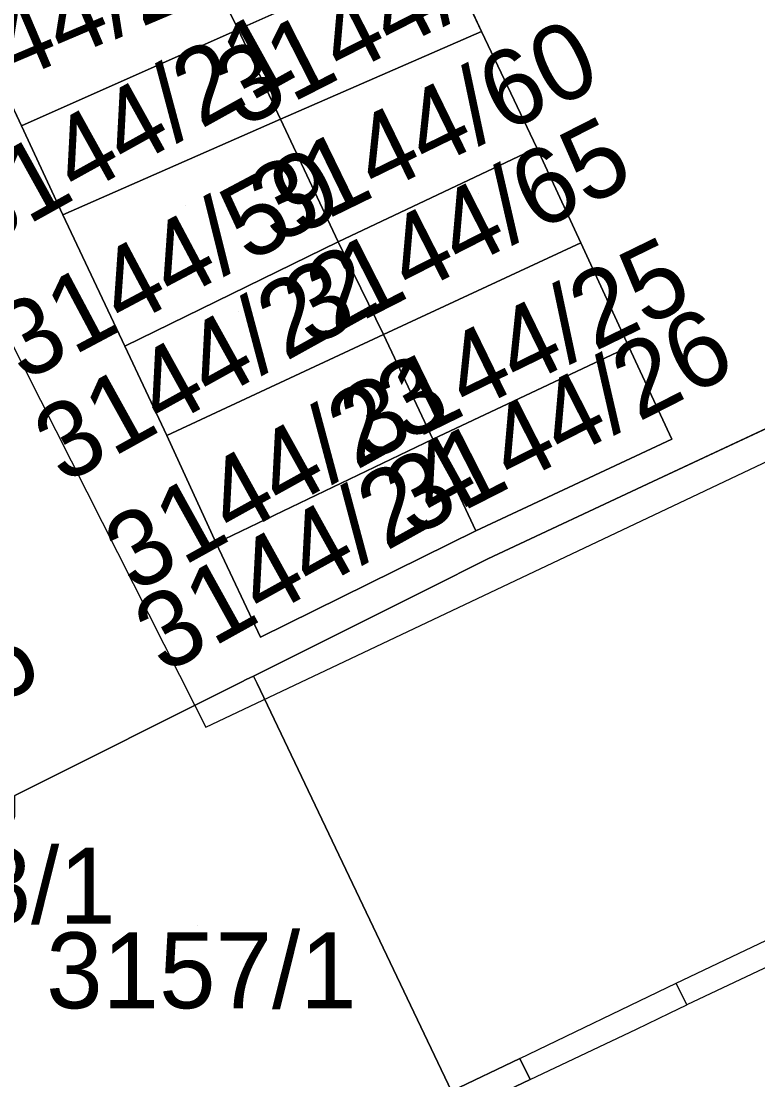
# Model space of a CAD drawing. Extents: x -264070 to -262271, y -1238894 to -1238141.
# Drawn here: x -262997.5 to -262978.09, y -1238467.13 to -1238439.24 of the extents above; entities that cross this region are included whole.
import ezdxf

# ---------------------------------------------------------------- set-up
doc = ezdxf.new("R2010")
doc.units = 0
for name, color, linetype in [('body_kn', 7, 'Continuous'), ('kladpar_druhypozemkov', 7, 'Continuous'), ('kladpar_hranice', 7, 'Continuous'), ('kladpar_parcelnecisla', 7, 'Continuous'), ('kladpar_plochy', 7, 'Continuous'), ('tarchy_linie', 7, 'Continuous'), ('zappar_hrandruhpozemk', 7, 'Continuous')]:
    doc.layers.add(name, color=color, linetype=linetype)

msp = doc.modelspace()

# ---------------------------------------------------------------- linework, layer by layer
at = {"layer": 'body_kn'}
for p, q in [((-262991.78, -1238439.46), (-262991.78, -1238439.46)), ((-262991.78, -1238439.46), (-262991.78, -1238439.46)), ((-262985.37, -1238439.52), (-262985.37, -1238439.52)), ((-262985.37, -1238439.52), (-262985.37, -1238439.52)), ((-262997.49, -1238442), (-262997.49, -1238442)), ((-262990.67, -1238441.83), (-262990.67, -1238441.83)), ((-262990.67, -1238441.83), (-262990.67, -1238441.83)), ((-262983.91, -1238442.58), (-262983.91, -1238442.58)), ((-262983.91, -1238442.58), (-262983.91, -1238442.58)), ((-262996.4, -1238444.35), (-262996.4, -1238444.35)), ((-262989.15, -1238445.06), (-262989.15, -1238445.06)), ((-262989.15, -1238445.06), (-262989.15, -1238445.06)), ((-262982.75, -1238445.08), (-262982.75, -1238445.08)), ((-262982.75, -1238445.08), (-262982.75, -1238445.08)), ((-262987.95, -1238447.5), (-262987.95, -1238447.5)), ((-262987.95, -1238447.5), (-262987.95, -1238447.5)), ((-262994.77, -1238447.81), (-262994.77, -1238447.81)), ((-262981.49, -1238447.82), (-262981.49, -1238447.82)), ((-262981.49, -1238447.82), (-262981.49, -1238447.82)), ((-262993.66, -1238450.16), (-262993.66, -1238450.16)), ((-262986.65, -1238450.26), (-262986.65, -1238450.26)), ((-262986.65, -1238450.26), (-262986.65, -1238450.26)), ((-262980.36, -1238450.26), (-262980.36, -1238450.26)), ((-262980.86, -1238451.37), (-262980.86, -1238451.37)), ((-262980.82, -1238452.25), (-262980.82, -1238452.25)), ((-262985.52, -1238452.67), (-262985.52, -1238452.67)), ((-262992.36, -1238453), (-262992.36, -1238453)), ((-262985.2, -1238453.41), (-262985.2, -1238453.41)), ((-262986.78, -1238454.2), (-262986.78, -1238454.2)), ((-262991.19, -1238455.47), (-262991.19, -1238455.47)), ((-262991.38, -1238456.5), (-262991.38, -1238456.5)), ((-262991.69, -1238456.65), (-262991.69, -1238456.65)), ((-262991.57, -1238456.59), (-262991.57, -1238456.59)), ((-262991.28, -1238456.69), (-262991.28, -1238456.69)), ((-262992.92, -1238457.27), (-262992.92, -1238457.27)), ((-262992.92, -1238457.27), (-262992.92, -1238457.27)), ((-262992.63, -1238457.84), (-262992.63, -1238457.84)), ((-262980.24, -1238464.59), (-262980.24, -1238464.59)), ((-262979.96, -1238465.16), (-262979.96, -1238465.16)), ((-262979.96, -1238465.16), (-262979.96, -1238465.16)), ((-262980.42, -1238465.38), (-262980.42, -1238465.38)), ((-262981.29, -1238465.8), (-262981.29, -1238465.8)), ((-262984.36, -1238466.57), (-262984.36, -1238466.57)), ((-262984.36, -1238466.57), (-262984.36, -1238466.57)), ((-262984.09, -1238467.13), (-262984.09, -1238467.13)), ((-262984.09, -1238467.13), (-262984.09, -1238467.13))]:
    msp.add_line(p, q, dxfattribs=at)
at = {"layer": 'kladpar_druhypozemkov'}
for p, q in [((-262994.57, -1238441.2), (-262994.57, -1238441.2)), ((-262986.96, -1238440.96), (-262986.96, -1238440.96)), ((-262985.46, -1238443.79), (-262985.46, -1238443.79)), ((-262993.17, -1238444.1), (-262993.17, -1238444.1)), ((-262983.29, -1238446.74), (-262983.29, -1238446.74)), ((-262991.77, -1238446.9), (-262991.77, -1238446.9)), ((-262983.2, -1238449.11), (-262983.2, -1238449.11)), ((-262992.21, -1238451.03), (-262992.21, -1238451.03)), ((-262988.77, -1238451.7), (-262988.77, -1238451.7)), ((-262992.85, -1238463.08), (-262992.85, -1238463.08))]:
    msp.add_line(p, q, dxfattribs=at)
at = {"layer": 'kladpar_hranice'}
for points in [[(-262994.77, -1238447.81), (-262993.66, -1238450.16), (-262992.36, -1238453), (-262991.19, -1238455.47), (-262985.52, -1238452.67), (-262980.36, -1238450.26), (-262981.49, -1238447.82), (-262982.75, -1238445.08), (-262983.91, -1238442.58), (-262985.37, -1238439.52), (-262986.49, -1238437.1), (-262987.81, -1238434.35), (-262989.09, -1238431.69), (-262990.18, -1238429.37), (-262995.49, -1238431.89), (-263000.98, -1238434.56), (-263000.02, -1238436.62), (-262998.8, -1238439.23), (-262997.49, -1238442), (-262996.4, -1238444.35), (-262994.77, -1238447.81)], [(-262987.81, -1238434.35), (-262986.49, -1238437.1), (-262991.78, -1238439.46), (-262993.13, -1238436.72), (-262987.81, -1238434.35)], [(-262993.13, -1238436.72), (-262991.78, -1238439.46), (-262997.49, -1238442), (-262998.8, -1238439.23), (-262993.13, -1238436.72)], [(-262986.49, -1238437.1), (-262985.37, -1238439.52), (-262990.67, -1238441.83), (-262991.78, -1238439.46), (-262986.49, -1238437.1)], [(-262991.78, -1238439.46), (-262990.67, -1238441.83), (-262996.4, -1238444.35), (-262997.49, -1238442), (-262991.78, -1238439.46)], [(-262985.37, -1238439.52), (-262983.91, -1238442.58), (-262989.15, -1238445.06), (-262990.67, -1238441.83), (-262985.37, -1238439.52)], [(-262990.67, -1238441.83), (-262989.15, -1238445.06), (-262994.77, -1238447.81), (-262996.4, -1238444.35), (-262990.67, -1238441.83)], [(-262983.91, -1238442.58), (-262982.75, -1238445.08), (-262987.95, -1238447.5), (-262989.15, -1238445.06), (-262983.91, -1238442.58)], [(-262965.85, -1238444.36), (-262980.86, -1238451.37), (-262985.2, -1238453.41), (-262986.78, -1238454.2), (-262991.38, -1238456.5), (-262991.57, -1238456.59), (-262991.69, -1238456.65), (-262997.67, -1238459.64)], [(-262985.45, -1238467.78), (-262984.09, -1238467.13), (-262984.36, -1238466.57), (-262986.16, -1238467.43), (-262991.28, -1238456.69), (-262991.38, -1238456.5), (-262986.78, -1238454.2), (-262985.2, -1238453.41), (-262980.86, -1238451.37), (-262965.85, -1238444.36), (-262960.55, -1238455.19), (-262970.92, -1238460.15), (-262970.64, -1238460.72)], [(-262989.15, -1238445.06), (-262987.95, -1238447.5), (-262993.66, -1238450.16), (-262994.77, -1238447.81), (-262989.15, -1238445.06)], [(-262982.75, -1238445.08), (-262981.49, -1238447.82), (-262986.65, -1238450.26), (-262987.95, -1238447.5), (-262982.75, -1238445.08)], [(-262987.95, -1238447.5), (-262986.65, -1238450.26), (-262992.36, -1238453), (-262993.66, -1238450.16), (-262987.95, -1238447.5)], [(-262981.49, -1238447.82), (-262980.36, -1238450.26), (-262985.52, -1238452.67), (-262986.65, -1238450.26), (-262981.49, -1238447.82)], [(-262986.65, -1238450.26), (-262985.52, -1238452.67), (-262991.19, -1238455.47), (-262992.36, -1238453), (-262986.65, -1238450.26)], [(-262997.67, -1238459.64), (-262991.69, -1238456.65), (-262991.57, -1238456.59), (-262991.38, -1238456.5), (-262991.28, -1238456.69), (-262986.16, -1238467.43), (-262984.36, -1238466.57), (-262984.09, -1238467.13), (-262985.45, -1238467.78), (-262986.48, -1238468.27), (-262987.33, -1238468.68), (-262993.76, -1238471.75), (-262994.32, -1238472.02), (-262995.94, -1238472.79), (-262997.16, -1238473.37), (-262997.34, -1238473.03), (-262997.51, -1238472.71), (-263001.85, -1238464.06), (-262998.96, -1238462.59), (-262998.09, -1238461.48), (-262997.67, -1238460.19), (-262997.67, -1238459.64)]]:
    msp.add_lwpolyline(points, dxfattribs=at)
at = {"layer": 'kladpar_plochy'}
for p, q in [((-262985.37, -1238439.52), (-262986.49, -1238437.1)), ((-262998.8, -1238439.23), (-262997.49, -1238442)), ((-262983.91, -1238442.58), (-262985.37, -1238439.52)), ((-262997.49, -1238442), (-262996.4, -1238444.35)), ((-262982.75, -1238445.08), (-262983.91, -1238442.58)), ((-262996.4, -1238444.35), (-262994.77, -1238447.81)), ((-262965.85, -1238444.36), (-262980.86, -1238451.37)), ((-262981.49, -1238447.82), (-262982.75, -1238445.08)), ((-262994.77, -1238447.81), (-262993.66, -1238450.16)), ((-262980.36, -1238450.26), (-262981.49, -1238447.82)), ((-262993.66, -1238450.16), (-262992.36, -1238453)), ((-262985.52, -1238452.67), (-262980.36, -1238450.26)), ((-262980.86, -1238451.37), (-262985.2, -1238453.41)), ((-262991.19, -1238455.47), (-262985.52, -1238452.67)), ((-262992.36, -1238453), (-262991.19, -1238455.47)), ((-262985.2, -1238453.41), (-262986.78, -1238454.2)), ((-262986.78, -1238454.2), (-262991.38, -1238456.5)), ((-262991.38, -1238456.5), (-262991.57, -1238456.59)), ((-262991.69, -1238456.65), (-262997.67, -1238459.64)), ((-262991.57, -1238456.59), (-262991.69, -1238456.65))]:
    msp.add_line(p, q, dxfattribs=at)
for points in [[(-262987.81, -1238434.35), (-262986.49, -1238437.1), (-262991.78, -1238439.46), (-262993.13, -1238436.72)], [(-262993.13, -1238436.72), (-262991.78, -1238439.46), (-262997.49, -1238442), (-262998.8, -1238439.23)], [(-262986.49, -1238437.1), (-262985.37, -1238439.52), (-262990.67, -1238441.83), (-262991.78, -1238439.46)], [(-262991.78, -1238439.46), (-262990.67, -1238441.83), (-262996.4, -1238444.35), (-262997.49, -1238442)], [(-262985.37, -1238439.52), (-262983.91, -1238442.58), (-262989.15, -1238445.06), (-262990.67, -1238441.83)], [(-262990.67, -1238441.83), (-262989.15, -1238445.06), (-262994.77, -1238447.81), (-262996.4, -1238444.35)], [(-262983.91, -1238442.58), (-262982.75, -1238445.08), (-262987.95, -1238447.5), (-262989.15, -1238445.06)], [(-262989.15, -1238445.06), (-262987.95, -1238447.5), (-262993.66, -1238450.16), (-262994.77, -1238447.81)], [(-262982.75, -1238445.08), (-262981.49, -1238447.82), (-262986.65, -1238450.26), (-262987.95, -1238447.5)], [(-262987.95, -1238447.5), (-262986.65, -1238450.26), (-262992.36, -1238453), (-262993.66, -1238450.16)], [(-262981.49, -1238447.82), (-262980.36, -1238450.26), (-262985.52, -1238452.67), (-262986.65, -1238450.26)], [(-262986.65, -1238450.26), (-262985.52, -1238452.67), (-262991.19, -1238455.47), (-262992.36, -1238453)], [(-262997.67, -1238459.64), (-262991.69, -1238456.65), (-262991.57, -1238456.59), (-262991.38, -1238456.5), (-262991.28, -1238456.69), (-262986.16, -1238467.43), (-262984.36, -1238466.57), (-262984.09, -1238467.13), (-262985.45, -1238467.78), (-262986.48, -1238468.27), (-262987.33, -1238468.68), (-262993.76, -1238471.75), (-262994.32, -1238472.02), (-262995.94, -1238472.79), (-262997.16, -1238473.37), (-262997.34, -1238473.03), (-262997.51, -1238472.71), (-263001.85, -1238464.06), (-262998.96, -1238462.59), (-262998.09, -1238461.48), (-262997.67, -1238460.19)]]:
    msp.add_lwpolyline(points, close=True, dxfattribs=at)
msp.add_lwpolyline([(-262985.45, -1238467.78), (-262984.09, -1238467.13), (-262984.36, -1238466.57), (-262986.16, -1238467.43), (-262991.28, -1238456.69), (-262991.38, -1238456.5), (-262986.78, -1238454.2), (-262985.2, -1238453.41), (-262980.86, -1238451.37), (-262965.85, -1238444.36), (-262960.55, -1238455.19), (-262970.92, -1238460.15), (-262970.64, -1238460.72), (-262968.87, -1238459.87), (-262967.78, -1238459.35), (-262960.38, -1238455.82), (-262958.54, -1238459.69), (-262958.35, -1238459.6), (-262955.74, -1238465.16), (-262955.92, -1238465.25), (-262954.06, -1238469.16)], dxfattribs=at)
at = {"layer": 'tarchy_linie'}
for points in [[(-263038.88, -1238420.23), (-263036.25, -1238420.98), (-263036.2, -1238421.05), (-263034.76, -1238422.91), (-263030.91, -1238427.88), (-263027.76, -1238431.97), (-263027.45, -1238432.37), (-263027.27, -1238432.6), (-263025.67, -1238434.67), (-263019.96, -1238444.31), (-263019.61, -1238444.14), (-263003.52, -1238436.33), (-262992.92, -1238457.27)], [(-262992.92, -1238457.27), (-262992.63, -1238457.84), (-262980.82, -1238452.25), (-262975.61, -1238449.78), (-262975.53, -1238449.87), (-262973.21, -1238452.81), (-262969.9, -1238460), (-262969.76, -1238460.29)]]:
    msp.add_lwpolyline(points, dxfattribs=at)
at = {"layer": 'zappar_hrandruhpozemk'}
for p, q in [((-262984.36, -1238466.57), (-262980.24, -1238464.59)), ((-262984.09, -1238467.13), (-262981.29, -1238465.8))]:
    msp.add_line(p, q, dxfattribs=at)
for points in [[(-262979.96, -1238465.16), (-262980.24, -1238464.59), (-262974.95, -1238462.07)], [(-262974.68, -1238462.65), (-262977.47, -1238463.98), (-262979.96, -1238465.16)], [(-262981.29, -1238465.8), (-262980.42, -1238465.38), (-262979.96, -1238465.16)]]:
    msp.add_lwpolyline(points, dxfattribs=at)

# ---------------------------------------------------------------- texts
at = {"layer": 'kladpar_parcelnecisla'}
for s, rotation, p in [('3144/19', 26, (-263001.166, -1238440.226)), ('3144/17', 27, (-262991.699, -1238442.084)), ('3144/20', 23, (-263000.506, -1238442.029)), ('3144/21', 29, (-262998.625, -1238445.344)), ('3144/60', 26, (-262990.812, -1238445.14)), ('3144/65', 27, (-262989.885, -1238447.847)), ('3144/59', 28, (-262997.436, -1238448.762)), ('3144/25', 26, (-262988.411, -1238450.888)), ('3144/22', 29, (-262996.389, -1238451.464)), ('3144/26', 27, (-262987.203, -1238452.851)), ('3144/23', 29, (-262994.533, -1238454.332)), ('3144/24', 29, (-262993.743, -1238456.462)), ('3144/36', 27, (-263005.477, -1238461.008))]:
    msp.add_text(s, height=2, rotation=rotation, dxfattribs=at).set_placement(p)
for s, p in [('3158/1', (-263003.19, -1238463.02)), ('3157/1', (-262996.841, -1238465.25))]:
    msp.add_text(s, height=2, dxfattribs=at).set_placement(p)

doc.saveas('drawing.dxf')
